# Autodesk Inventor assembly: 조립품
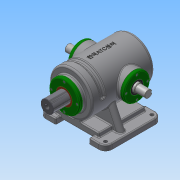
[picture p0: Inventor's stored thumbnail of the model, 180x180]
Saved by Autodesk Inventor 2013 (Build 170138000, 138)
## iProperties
Created: 2018-06
Part Number: 조립품
Document SubType Name: Assembly
Designer: Administrator
Author: Administrator
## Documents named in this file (13)
- C:\Users\Administrator\Desktop\380628V1014\조립품.iam
- C:\Users\Administrator\Desktop\380628V1014\본체.ipt
- C:\Users\Administrator\Desktop\380628V1014\가변 스프링.ipt
- C:\Users\Administrator\Desktop\380628V1014\베어링 6205.ipt
- 베어링 6205.ipt
- C:\Users\Administrator\Desktop\380628V1014\볼트 M4.ipt
- C:\Users\Administrator\Desktop\380628V1014\부시.ipt
- C:\Users\Administrator\Desktop\380628V1014\슬라이드 커버.ipt
- C:\Users\Administrator\Desktop\380628V1014\슬라이드.ipt
- C:\Users\Administrator\Desktop\380628V1014\오일실.ipt
- 오일실.ipt
- C:\Users\Administrator\Desktop\380628V1014\축 커버.ipt
- C:\Users\Administrator\Desktop\380628V1014\편심축.ipt
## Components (1 placed, 1 different names)
1. 가변 스프링:1
